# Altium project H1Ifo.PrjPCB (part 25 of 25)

## Sheet IfoSqz5.SchDoc: D1800185
size C; Engineer: Daniel Sigg; DocumentNumber: 10; Revision: 4; SheetNumber: 10; SheetTotal: 10
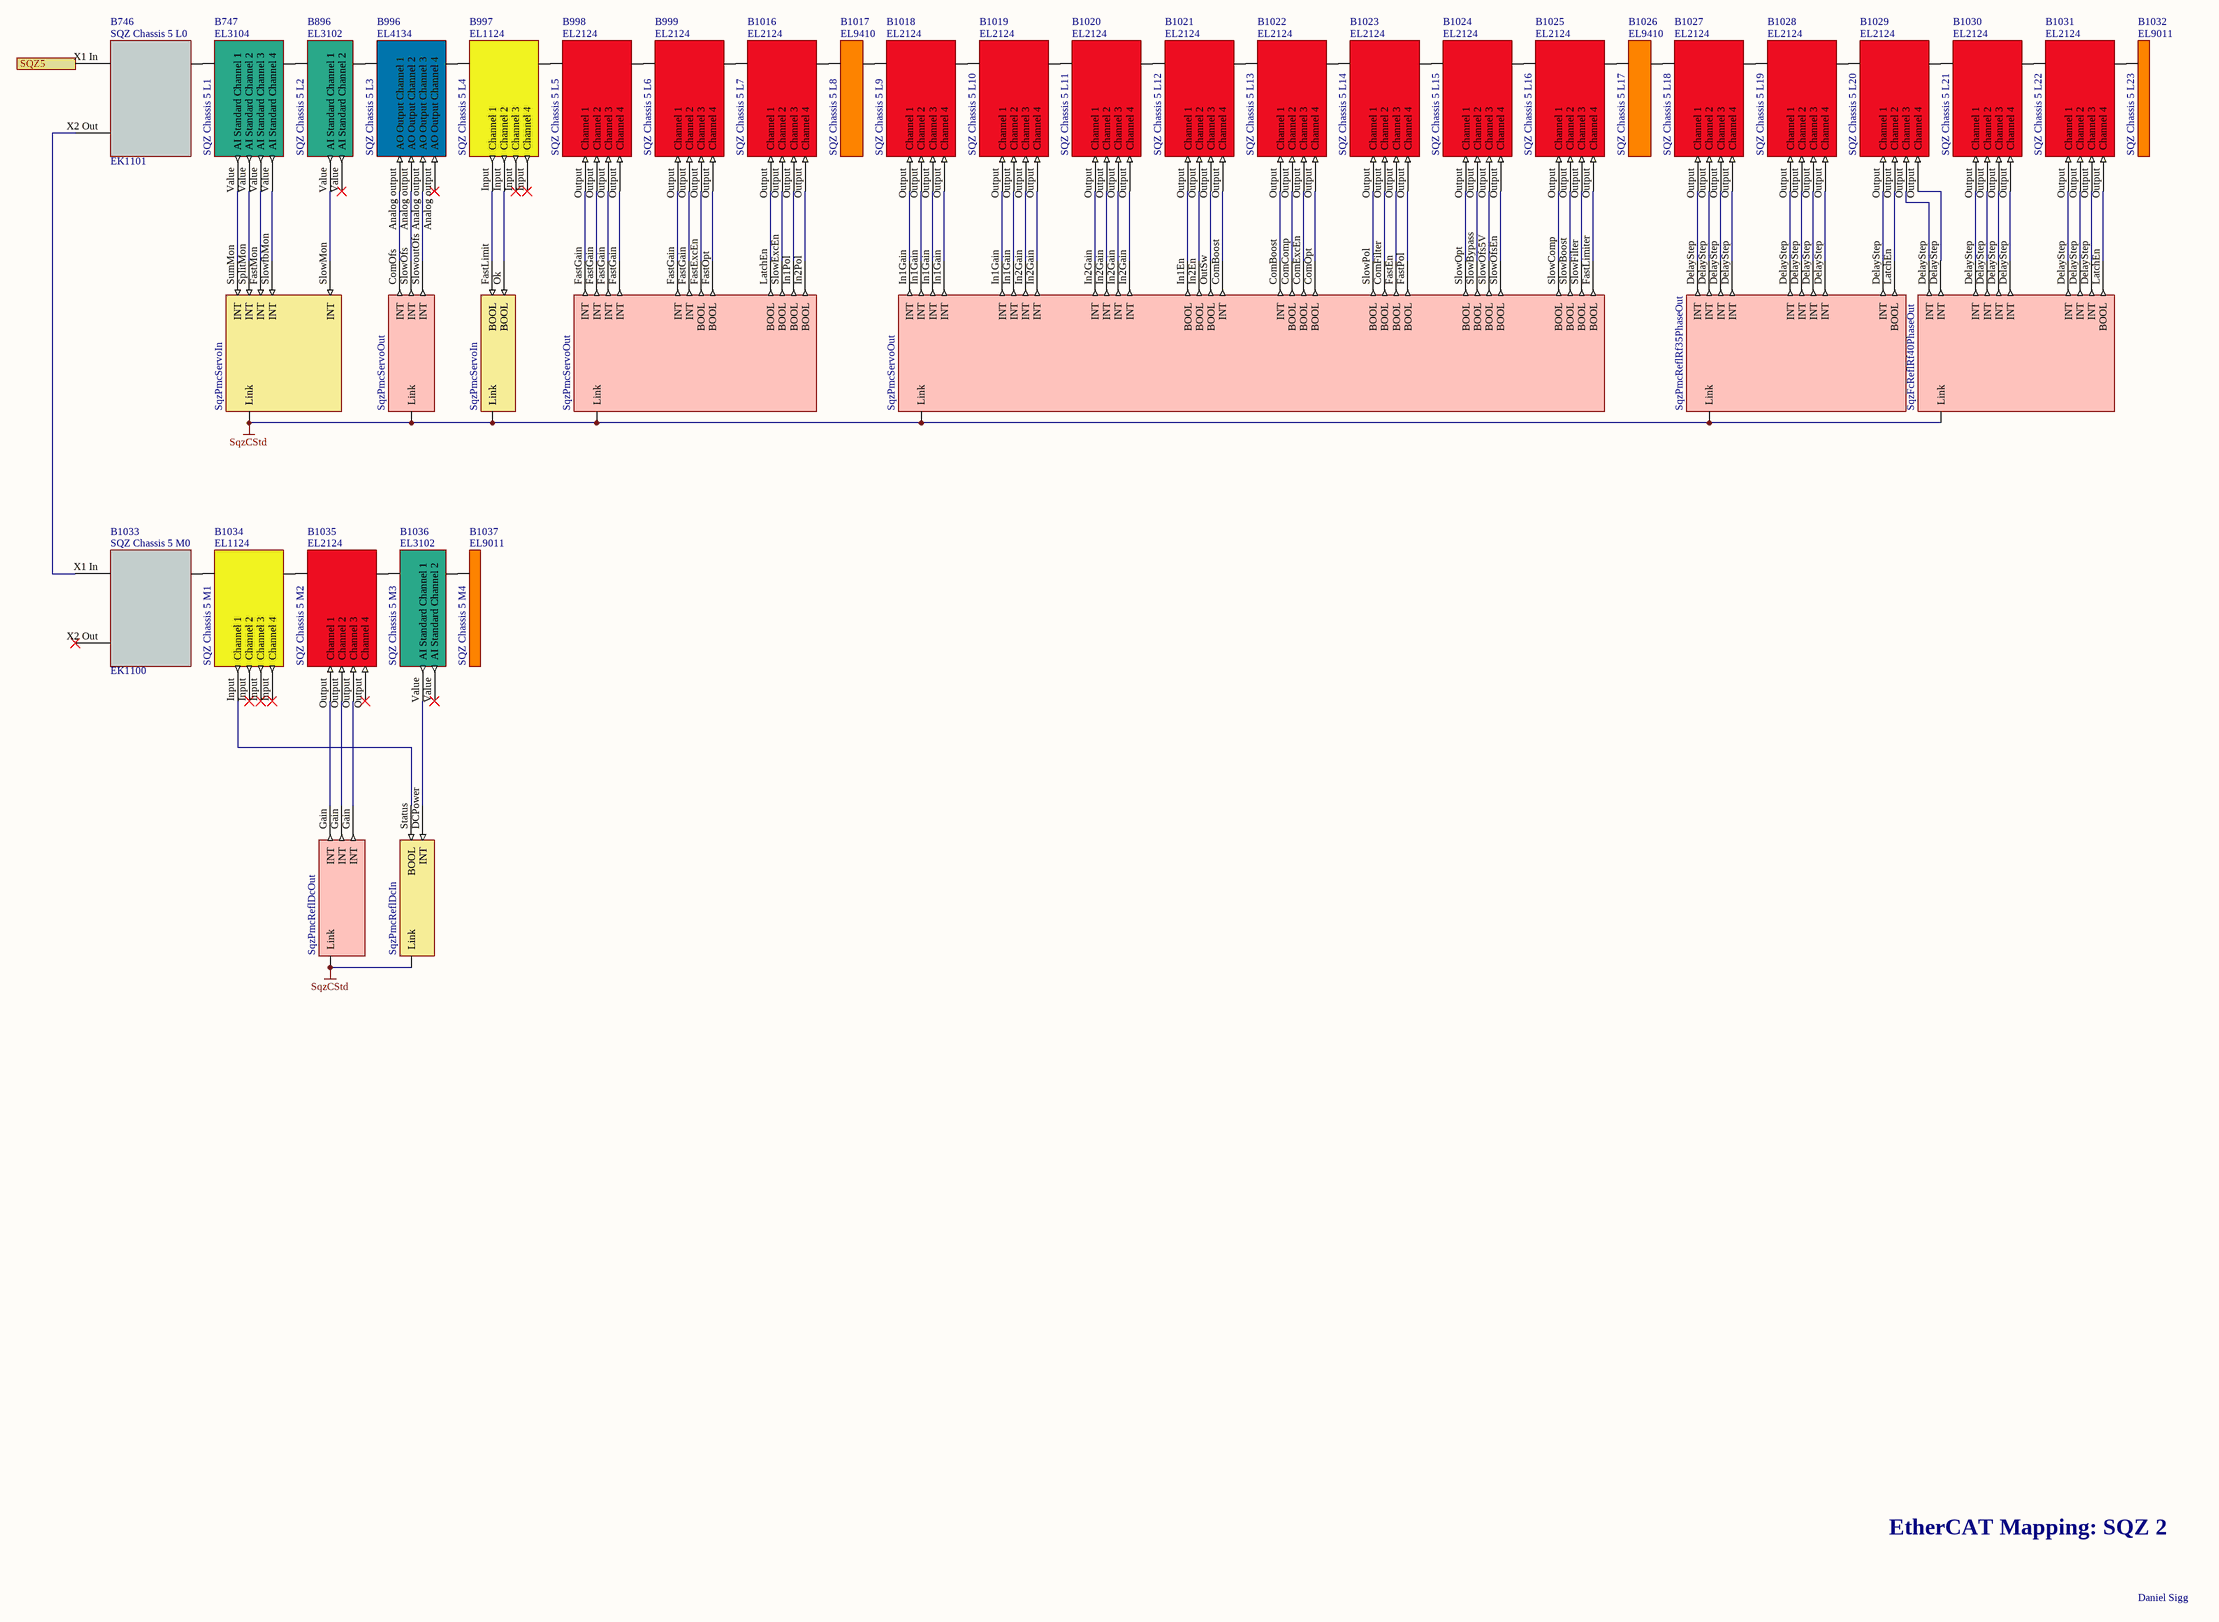
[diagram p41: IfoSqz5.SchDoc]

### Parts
(Parts that share a designator on the sheet are numbered #1, #2 ... from top to bottom, then left to right.)
B746#2  SQZ Chassis 5 L0  Part Number: EK1101
B747#2  SQZ Chassis 5 L1  Part Number: EL3104  (mechanical)
B896#3  SQZ Chassis 5 L2  Part Number: EL3102  (mechanical)
B996#2  SQZ Chassis 5 L3  Part Number: EL4134  (mechanical)
B997#2  SQZ Chassis 5 L4  Part Number: EL1124  (mechanical)
B998#2  SQZ Chassis 5 L5  Part Number: EL2124  (mechanical)
B999#2  SQZ Chassis 5 L6  Part Number: EL2124  (mechanical)
B1016#2  SQZ Chassis 5 L7  Part Number: EL2124  (mechanical)
B1017#2  SQZ Chassis 5 L8  Part Number: EL9410  (mechanical)
B1018#2  SQZ Chassis 5 L9  Part Number: EL2124  (mechanical)
B1019#2  SQZ Chassis 5 L10  Part Number: EL2124  (mechanical)
B1020#3  SQZ Chassis 5 L11  Part Number: EL2124  (mechanical)
B1021#2  SQZ Chassis 5 L12  Part Number: EL2124  (mechanical)
B1022#2  SQZ Chassis 5 L13  Part Number: EL2124  (mechanical)
B1023#2  SQZ Chassis 5 L14  Part Number: EL2124  (mechanical)
B1024#2  SQZ Chassis 5 L15  Part Number: EL2124  (mechanical)
B1025  SQZ Chassis 5 L16  Part Number: EL2124  (mechanical)
B1026  SQZ Chassis 5 L17  Part Number: EL9410  (mechanical)
B1027  SQZ Chassis 5 L18  Part Number: EL2124  (mechanical)
B1028  SQZ Chassis 5 L19  Part Number: EL2124  (mechanical)
B1029  SQZ Chassis 5 L20  Part Number: EL2124  (mechanical)
B1030  SQZ Chassis 5 L21  Part Number: EL2124  (mechanical)
B1031  SQZ Chassis 5 L22  Part Number: EL2124  (mechanical)
B1032  SQZ Chassis 5 L23  Part Number: EL9011  (mechanical)
B1033  SQZ Chassis 5 M0  Part Number: EK1100
B1034  SQZ Chassis 5 M1  Part Number: EL1124  (mechanical)
B1035  SQZ Chassis 5 M2  Part Number: EL2124  (mechanical)
B1036  SQZ Chassis 5 M3  Part Number: EL3102  (mechanical)
B1037  SQZ Chassis 5 M4  Part Number: EL9011  (mechanical)
V868  SqzPmcServoIn  (parts A,B of 2)  (no BOM)
V869  SqzPmcReflRf35PhaseOut  (no BOM)
V870  SqzFcReflRf40PhaseOut  (no BOM)
V871  SqzPmcReflDcOut  (no BOM)
V872  SqzPmcReflDcIn  (no BOM)
V873  SqzPmcServoOut  (parts A,B,C of 3)  (no BOM)

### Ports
SQZ5

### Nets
SqzCStd: V868.0(Link) V868.1(Link) V869.?1(Link) V870.?1(Link) V871.0(Link) V872.1(Link) V873.0(Link) V873.1(Link) V873.2(Link)
NetB746#2_Ebus: B746#2.Ebus(B) B747#2.Ebus(A)
NetB746#2_X1 In: B746#2.X1_In(A) ; port SQZ5
NetB746#2_X2 Out: B746#2.X2_Out(C) B1033.X1_In(A)
NetB747#2_Ebus: B747#2.Ebus(B) B896#3.Ebus(A)
NetB747#2_Value: B747#2.Value(AI_Standard_Channel_1) V868.SumMon(INT)
NetB747#2_Value: B747#2.Value(AI_Standard_Channel_2) V868.SplitMon(INT)  [a separate net that carries the same name]
NetB747#2_Value: B747#2.Value(AI_Standard_Channel_3) V868.FastMon(INT)  [a separate net that carries the same name]
NetB747#2_Value: B747#2.Value(AI_Standard_Channel_4) V868.SlowfbMon(INT)  [a separate net that carries the same name]
NetB896#3_Ebus: B896#3.Ebus(B) B996#2.Ebus(A)
NetB896#3_Value: B896#3.Value(AI_Standard_Channel_1) V868.SlowMon(INT)
NetB996#2_Analog output: B996#2.Analog_output(AO_Output_Channel_1) V873.ComOfs(INT)
NetB996#2_Analog output: B996#2.Analog_output(AO_Output_Channel_2) V873.SlowOfs(INT)  [a separate net that carries the same name]
NetB996#2_Analog output: B996#2.Analog_output(AO_Output_Channel_3) V873.SlowoutOfs(INT)  [a separate net that carries the same name]
NetB996#2_Ebus: B996#2.Ebus(B) B997#2.Ebus(A)
NetB997#2_Ebus: B997#2.Ebus(B) B998#2.Ebus(A)
NetB997#2_Input: B997#2.Input(Channel_1) V868.FastLimit(BOOL)
NetB997#2_Input: B997#2.Input(Channel_2) V868.Ok(BOOL)  [a separate net that carries the same name]
NetB998#2_Ebus: B998#2.Ebus(B) B999#2.Ebus(A)
NetB998#2_Output: B998#2.Output(Channel_1) V873.FastGain(INT)
NetB998#2_Output: B998#2.Output(Channel_2) V873.FastGain(INT)  [a separate net that carries the same name]
NetB998#2_Output: B998#2.Output(Channel_3) V873.FastGain(INT)  [a separate net that carries the same name]
NetB998#2_Output: B998#2.Output(Channel_4) V873.FastGain(INT)  [a separate net that carries the same name]
NetB999#2_Ebus: B999#2.Ebus(B) B1016#2.Ebus(A)
NetB999#2_Output: B999#2.Output(Channel_1) V873.FastGain(INT)
NetB999#2_Output: B999#2.Output(Channel_2) V873.FastGain(INT)  [a separate net that carries the same name]
NetB999#2_Output: B999#2.Output(Channel_3) V873.FastExcEn(BOOL)  [a separate net that carries the same name]
NetB999#2_Output: B999#2.Output(Channel_4) V873.FastOpt(BOOL)  [a separate net that carries the same name]
NetB1016#2_Ebus: B1016#2.Ebus(B) B1017#2.Ebus(A)
NetB1016#2_Output: B1016#2.Output(Channel_1) V873.LatchEn(BOOL)
NetB1016#2_Output: B1016#2.Output(Channel_2) V873.SlowExcEn(BOOL)  [a separate net that carries the same name]
NetB1016#2_Output: B1016#2.Output(Channel_3) V873.In1Pol(BOOL)  [a separate net that carries the same name]
NetB1016#2_Output: B1016#2.Output(Channel_4) V873.In2Pol(BOOL)  [a separate net that carries the same name]
NetB1017#2_Ebus: B1017#2.Ebus(B) B1018#2.Ebus(A)
NetB1018#2_Ebus: B1018#2.Ebus(B) B1019#2.Ebus(A)
NetB1018#2_Output: B1018#2.Output(Channel_1) V873.In1Gain(INT)
NetB1018#2_Output: B1018#2.Output(Channel_2) V873.In1Gain(INT)  [a separate net that carries the same name]
NetB1018#2_Output: B1018#2.Output(Channel_3) V873.In1Gain(INT)  [a separate net that carries the same name]
NetB1018#2_Output: B1018#2.Output(Channel_4) V873.In1Gain(INT)  [a separate net that carries the same name]
NetB1019#2_Ebus: B1019#2.Ebus(B) B1020#3.Ebus(A)
NetB1019#2_Output: B1019#2.Output(Channel_1) V873.In1Gain(INT)
NetB1019#2_Output: B1019#2.Output(Channel_2) V873.In1Gain(INT)  [a separate net that carries the same name]
NetB1019#2_Output: B1019#2.Output(Channel_3) V873.In2Gain(INT)  [a separate net that carries the same name]
NetB1019#2_Output: B1019#2.Output(Channel_4) V873.In2Gain(INT)  [a separate net that carries the same name]
NetB1020#3_Ebus: B1020#3.Ebus(B) B1021#2.Ebus(A)
NetB1020#3_Output: B1020#3.Output(Channel_1) V873.In2Gain(INT)
NetB1020#3_Output: B1020#3.Output(Channel_2) V873.In2Gain(INT)  [a separate net that carries the same name]
NetB1020#3_Output: B1020#3.Output(Channel_3) V873.In2Gain(INT)  [a separate net that carries the same name]
NetB1020#3_Output: B1020#3.Output(Channel_4) V873.In2Gain(INT)  [a separate net that carries the same name]
NetB1021#2_Ebus: B1021#2.Ebus(B) B1022#2.Ebus(A)
NetB1021#2_Output: B1021#2.Output(Channel_1) V873.In1En(BOOL)
NetB1021#2_Output: B1021#2.Output(Channel_2) V873.In2En(BOOL)  [a separate net that carries the same name]
NetB1021#2_Output: B1021#2.Output(Channel_3) V873.OutSw(BOOL)  [a separate net that carries the same name]
NetB1021#2_Output: B1021#2.Output(Channel_4) V873.ComBoost(INT)  [a separate net that carries the same name]
NetB1022#2_Ebus: B1022#2.Ebus(B) B1023#2.Ebus(A)
NetB1022#2_Output: B1022#2.Output(Channel_1) V873.ComBoost(INT)
NetB1022#2_Output: B1022#2.Output(Channel_2) V873.ComComp(BOOL)  [a separate net that carries the same name]
NetB1022#2_Output: B1022#2.Output(Channel_3) V873.ComExcEn(BOOL)  [a separate net that carries the same name]
NetB1022#2_Output: B1022#2.Output(Channel_4) V873.ComOpt(BOOL)  [a separate net that carries the same name]
NetB1023#2_Ebus: B1023#2.Ebus(B) B1024#2.Ebus(A)
NetB1023#2_Output: B1023#2.Output(Channel_1) V873.SlowPol(BOOL)
NetB1023#2_Output: B1023#2.Output(Channel_2) V873.ComFilter(BOOL)  [a separate net that carries the same name]
NetB1023#2_Output: B1023#2.Output(Channel_3) V873.FastEn(BOOL)  [a separate net that carries the same name]
NetB1023#2_Output: B1023#2.Output(Channel_4) V873.FastPol(BOOL)  [a separate net that carries the same name]
NetB1024#2_Ebus: B1024#2.Ebus(B) B1025.Ebus(A)
NetB1024#2_Output: B1024#2.Output(Channel_1) V873.SlowOpt(BOOL)
NetB1024#2_Output: B1024#2.Output(Channel_2) V873.SlowBypass(BOOL)  [a separate net that carries the same name]
NetB1024#2_Output: B1024#2.Output(Channel_3) V873.SlowOfs5V(BOOL)  [a separate net that carries the same name]
NetB1024#2_Output: B1024#2.Output(Channel_4) V873.SlowOfsEn(BOOL)  [a separate net that carries the same name]
NetB1025_Ebus: B1025.Ebus(B) B1026.Ebus(A)
NetB1025_Output: B1025.Output(Channel_1) V873.SlowComp(BOOL)
NetB1025_Output: B1025.Output(Channel_2) V873.SlowBoost(BOOL)  [a separate net that carries the same name]
NetB1025_Output: B1025.Output(Channel_3) V873.SlowFilter(BOOL)  [a separate net that carries the same name]
NetB1025_Output: B1025.Output(Channel_4) V873.FastLimiter(BOOL)  [a separate net that carries the same name]
NetB1026_Ebus: B1026.Ebus(B) B1027.Ebus(A)
NetB1027_Ebus: B1027.Ebus(B) B1028.Ebus(A)
NetB1027_Output: B1027.Output(Channel_1) V869.DelayStep(INT)
NetB1027_Output: B1027.Output(Channel_2) V869.DelayStep(INT)  [a separate net that carries the same name]
NetB1027_Output: B1027.Output(Channel_3) V869.DelayStep(INT)  [a separate net that carries the same name]
NetB1027_Output: B1027.Output(Channel_4) V869.DelayStep(INT)  [a separate net that carries the same name]
NetB1028_Ebus: B1028.Ebus(B) B1029.Ebus(A)
NetB1028_Output: B1028.Output(Channel_1) V869.DelayStep(INT)
NetB1028_Output: B1028.Output(Channel_2) V869.DelayStep(INT)  [a separate net that carries the same name]
NetB1028_Output: B1028.Output(Channel_3) V869.DelayStep(INT)  [a separate net that carries the same name]
NetB1028_Output: B1028.Output(Channel_4) V869.DelayStep(INT)  [a separate net that carries the same name]
NetB1029_Ebus: B1029.Ebus(B) B1030.Ebus(A)
NetB1029_Output: B1029.Output(Channel_1) V869.DelayStep(INT)
NetB1029_Output: B1029.Output(Channel_2) V869.LatchEn(BOOL)  [a separate net that carries the same name]
NetB1029_Output: B1029.Output(Channel_3) V870.DelayStep(INT)  [a separate net that carries the same name]
NetB1029_Output: B1029.Output(Channel_4) V870.DelayStep(INT)  [a separate net that carries the same name]
NetB1030_Ebus: B1030.Ebus(B) B1031.Ebus(A)
NetB1030_Output: B1030.Output(Channel_1) V870.DelayStep(INT)
NetB1030_Output: B1030.Output(Channel_2) V870.DelayStep(INT)  [a separate net that carries the same name]
NetB1030_Output: B1030.Output(Channel_3) V870.DelayStep(INT)  [a separate net that carries the same name]
NetB1030_Output: B1030.Output(Channel_4) V870.DelayStep(INT)  [a separate net that carries the same name]
NetB1031_Ebus: B1031.Ebus(B) B1032.Ebus(A)
NetB1031_Output: B1031.Output(Channel_1) V870.DelayStep(INT)
NetB1031_Output: B1031.Output(Channel_2) V870.DelayStep(INT)  [a separate net that carries the same name]
NetB1031_Output: B1031.Output(Channel_3) V870.DelayStep(INT)  [a separate net that carries the same name]
NetB1031_Output: B1031.Output(Channel_4) V870.LatchEn(BOOL)  [a separate net that carries the same name]
NetB1033_Ebus: B1033.Ebus(B) B1034.Ebus(A)
NetB1034_Ebus: B1034.Ebus(B) B1035.Ebus(A)
NetB1034_Input: B1034.Input(Channel_1) V872.Status(BOOL)
NetB1035_Ebus: B1035.Ebus(B) B1036.Ebus(A)
NetB1035_Output: B1035.Output(Channel_1) V871.Gain(INT)
NetB1035_Output: B1035.Output(Channel_2) V871.Gain(INT)  [a separate net that carries the same name]
NetB1035_Output: B1035.Output(Channel_3) V871.Gain(INT)  [a separate net that carries the same name]
NetB1036_Ebus: B1036.Ebus(B) B1037.Ebus(A)
NetB1036_Value: B1036.Value(AI_Standard_Channel_1) V872.DCPower(INT)

Not connected (* = marked no-connect by the designer): B1033 X2 Out(C)*

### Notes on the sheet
- EtherCAT Mapping: SQZ 2
- Daniel Sigg

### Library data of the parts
B746#2 = CouplerEK1101: EtherCAT Coupler; Rail: Left; BoxNextB: LKYXOSUU; BoxNextC: LKDMUIJW; BoxPrev: CWDKXLUE; PortPrevFull: 1240/C; PortPrevShort: C 'X2 Out'; Fullname: TIID^Vertex Squeezer (EtherCAT)^SQZ Chassis 5 L0 (EK1101); BoxPorts: Junction; BoxAddr: 1253; Disabled: False
B747#2 = TerminalEL3104: EtherCAT Terminal EL3104 4-chn Analog Input; Rail: Left; BoxNextB: JVLGVOLS; BoxPrev: JQVLJOFM; PortPrevFull: 1253/B; PortPrevShort: B; Fullname: TIID^Vertex Squeezer (EtherCAT)^SQZ Chassis 5 L0 (EK1101)^SQZ Chassis 5 L1 (EL3104); BoxAddr: 1254; Disabled: False
B896#3 = TerminalEL3102: EtherCAT Terminal EL3102 2-chn Analog Input; Rail: Left; BoxNextB: BEMJPELD; BoxPrev: LKYXOSUU; PortPrevFull: 1254/B; PortPrevShort: B; Fullname: TIID^Vertex Squeezer (EtherCAT)^SQZ Chassis 5 L0 (EK1101)^SQZ Chassis 5 L2 (EL3102); BoxAddr: 1255; Disabled: False
B996#2 = TerminalEL4134: EtherCAT Terminal EL4134 4-chn Analog Ouput; Rail: Left; BoxNextB: KFGECLUF; BoxPrev: JVLGVOLS; PortPrevFull: 1255/B; PortPrevShort: B; Fullname: TIID^Vertex Squeezer (EtherCAT)^SQZ Chassis 5 L0 (EK1101)^SQZ Chassis 5 L3 (EL4134); BoxAddr: 1256; Disabled: False
B997#2 = TerminalEL1124: EtherCAT Terminal EL1124 4-chn Digital Input; Rail: Left; BoxNextB: XXYSQFDN; BoxPrev: BEMJPELD; PortPrevFull: 1256/B; PortPrevShort: B; Fullname: TIID^Vertex Squeezer (EtherCAT)^SQZ Chassis 5 L0 (EK1101)^SQZ Chassis 5 L4 (EL1124); BoxAddr: 1257; Disabled: False
B998#2 = TerminalEL2124: EtherCAT Terminal EL2124 4-chn Digital Ouput; Rail: Left; BoxNextB: NKADTWFC; BoxPrev: KFGECLUF; PortPrevFull: 1257/B; PortPrevShort: B; Fullname: TIID^Vertex Squeezer (EtherCAT)^SQZ Chassis 5 L0 (EK1101)^SQZ Chassis 5 L5 (EL2124); BoxAddr: 1258; Disabled: False
B999#2 = TerminalEL2124: EtherCAT Terminal EL2124 4-chn Digital Ouput; Rail: Left; BoxNextB: BBCHXAVO; BoxPrev: XXYSQFDN; PortPrevFull: 1258/B; PortPrevShort: B; Fullname: TIID^Vertex Squeezer (EtherCAT)^SQZ Chassis 5 L0 (EK1101)^SQZ Chassis 5 L6 (EL2124); BoxAddr: 1259; Disabled: False
B1016#2 = TerminalEL2124: EtherCAT Terminal EL2124 4-chn Digital Ouput; Rail: Left; BoxNextB: KRYXCAPR; BoxPrev: NKADTWFC; PortPrevFull: 1259/B; PortPrevShort: B; Fullname: TIID^Vertex Squeezer (EtherCAT)^SQZ Chassis 5 L0 (EK1101)^SQZ Chassis 5 L7 (EL2124); BoxAddr: 1260; Disabled: False
B1017#2 = TerminalEL9410: EtherCAT Terminal EL9410 Power; Rail: Left; BoxNextB: IYADOACW; BoxPrev: BBCHXAVO; PortPrevFull: 1260/B; PortPrevShort: B; Fullname: TIID^Vertex Squeezer (EtherCAT)^SQZ Chassis 5 L0 (EK1101)^SQZ Chassis 5 L8 (EL9410); BoxAddr: 1261; Disabled: False
B1018#2 = TerminalEL2124: EtherCAT Terminal EL2124 4-chn Digital Ouput; Rail: Left; BoxNextB: FWAQFTHP; BoxPrev: KRYXCAPR; PortPrevFull: 1261/B; PortPrevShort: B; Fullname: TIID^Vertex Squeezer (EtherCAT)^SQZ Chassis 5 L0 (EK1101)^SQZ Chassis 5 L9 (EL2124); BoxAddr: 1262; Disabled: False
B1019#2 = TerminalEL2124: EtherCAT Terminal EL2124 4-chn Digital Ouput; Rail: Left; BoxNextB: YNBMSKFQ; BoxPrev: IYADOACW; PortPrevFull: 1262/B; PortPrevShort: B; Fullname: TIID^Vertex Squeezer (EtherCAT)^SQZ Chassis 5 L0 (EK1101)^SQZ Chassis 5 L10 (EL2124); BoxAddr: 1263; Disabled: False
B1020#3 = TerminalEL2124: EtherCAT Terminal EL2124 4-chn Digital Ouput; Rail: Left; BoxNextB: RSFOLQSB; BoxPrev: FWAQFTHP; PortPrevFull: 1263/B; PortPrevShort: B; Fullname: TIID^Vertex Squeezer (EtherCAT)^SQZ Chassis 5 L0 (EK1101)^SQZ Chassis 5 L11 (EL2124); BoxAddr: 1264; Disabled: False
B1021#2 = TerminalEL2124: EtherCAT Terminal EL2124 4-chn Digital Ouput; Rail: Left; BoxNextB: WUOQKASJ; BoxPrev: YNBMSKFQ; PortPrevFull: 1264/B; PortPrevShort: B; Fullname: TIID^Vertex Squeezer (EtherCAT)^SQZ Chassis 5 L0 (EK1101)^SQZ Chassis 5 L12 (EL2124); BoxAddr: 1265; Disabled: False
B1022#2 = TerminalEL2124: EtherCAT Terminal EL2124 4-chn Digital Ouput; Rail: Left; BoxNextB: RPVQQTWJ; BoxPrev: RSFOLQSB; PortPrevFull: 1265/B; PortPrevShort: B; Fullname: TIID^Vertex Squeezer (EtherCAT)^SQZ Chassis 5 L0 (EK1101)^SQZ Chassis 5 L13 (EL2124); BoxAddr: 1266; Disabled: False
B1023#2 = TerminalEL2124: EtherCAT Terminal EL2124 4-chn Digital Ouput; Rail: Left; BoxNextB: MLVVBFMT; BoxPrev: WUOQKASJ; PortPrevFull: 1266/B; PortPrevShort: B; Fullname: TIID^Vertex Squeezer (EtherCAT)^SQZ Chassis 5 L0 (EK1101)^SQZ Chassis 5 L14 (EL2124); BoxAddr: 1267; Disabled: False
B1024#2 = TerminalEL2124: EtherCAT Terminal EL2124 4-chn Digital Ouput; Rail: Left; BoxNextB: SGWXRRPH; BoxPrev: RPVQQTWJ; PortPrevFull: 1267/B; PortPrevShort: B; Fullname: TIID^Vertex Squeezer (EtherCAT)^SQZ Chassis 5 L0 (EK1101)^SQZ Chassis 5 L15 (EL2124); BoxAddr: 1268; Disabled: False
B1025 = TerminalEL2124: EtherCAT Terminal EL2124 4-chn Digital Ouput; Rail: Left; BoxNextB: CTCISQMT; BoxPrev: MLVVBFMT; PortPrevFull: 1268/B; PortPrevShort: B; Fullname: TIID^Vertex Squeezer (EtherCAT)^SQZ Chassis 5 L0 (EK1101)^SQZ Chassis 5 L16 (EL2124); BoxAddr: 1269; Disabled: False
B1026 = TerminalEL9410: EtherCAT Terminal EL9410 Power; Rail: Left; BoxNextB: AVCHSOEV; BoxPrev: SGWXRRPH; PortPrevFull: 1269/B; PortPrevShort: B; Fullname: TIID^Vertex Squeezer (EtherCAT)^SQZ Chassis 5 L0 (EK1101)^SQZ Chassis 5 L17 (EL9410); BoxAddr: 1270; Disabled: False
B1027 = TerminalEL2124: EtherCAT Terminal EL2124 4-chn Digital Ouput; Rail: Left; BoxNextB: RNOAQAFY; BoxPrev: CTCISQMT; PortPrevFull: 1270/B; PortPrevShort: B; Fullname: TIID^Vertex Squeezer (EtherCAT)^SQZ Chassis 5 L0 (EK1101)^SQZ Chassis 5 L18 (EL2124); BoxAddr: 1271; Disabled: False
B1028 = TerminalEL2124: EtherCAT Terminal EL2124 4-chn Digital Ouput; Rail: Left; BoxNextB: MVUKHKFD; BoxPrev: AVCHSOEV; PortPrevFull: 1271/B; PortPrevShort: B; Fullname: TIID^Vertex Squeezer (EtherCAT)^SQZ Chassis 5 L0 (EK1101)^SQZ Chassis 5 L19 (EL2124); BoxAddr: 1272; Disabled: False
B1029 = TerminalEL2124: EtherCAT Terminal EL2124 4-chn Digital Ouput; Rail: Left; BoxNextB: BATIWAGG; BoxPrev: RNOAQAFY; PortPrevFull: 1272/B; PortPrevShort: B; Fullname: TIID^Vertex Squeezer (EtherCAT)^SQZ Chassis 5 L0 (EK1101)^SQZ Chassis 5 L20 (EL2124); BoxAddr: 1273; Disabled: False
B1030 = TerminalEL2124: EtherCAT Terminal EL2124 4-chn Digital Ouput; Rail: Left; BoxNextB: OYHVUHQP; BoxPrev: MVUKHKFD; PortPrevFull: 1273/B; PortPrevShort: B; Fullname: TIID^Vertex Squeezer (EtherCAT)^SQZ Chassis 5 L0 (EK1101)^SQZ Chassis 5 L21 (EL2124); BoxAddr: 1274; Disabled: False
B1031 = TerminalEL2124: EtherCAT Terminal EL2124 4-chn Digital Ouput; Rail: Left; BoxNextB: ODKNBTAG; BoxPrev: BATIWAGG; PortPrevFull: 1274/B; PortPrevShort: B; Fullname: TIID^Vertex Squeezer (EtherCAT)^SQZ Chassis 5 L0 (EK1101)^SQZ Chassis 5 L22 (EL2124); BoxAddr: 1275; Disabled: False
B1032 = TerminalEL9011: EtherCAT Terminal EL9011 End; BoxType: TerminalPassive; Rail: Left; BoxPrev: OYHVUHQP; PortPrevShort: B; Fullname: TIID^Vertex Squeezer (EtherCAT)^SQZ Chassis 5 L0 (EK1101)^SQZ Chassis 5 L23 (EL9011); Disabled: False
B1033 = CouplerEK1100: EtherCAT Coupler; Rail: Middle; BoxNextB: FLDENWVA; BoxPrev: JQVLJOFM; PortPrevFull: 1253/C; PortPrevShort: C 'X2 Out'; Fullname: TIID^Vertex Squeezer (EtherCAT)^SQZ Chassis 5 M0 (EK1100); BoxPorts: Junction; BoxAddr: 1276; Disabled: False
B1034 = TerminalEL1124: EtherCAT Terminal EL1124 4-chn Digital Input; Rail: Middle; BoxNextB: PTDDMXXB; BoxPrev: LKDMUIJW; PortPrevFull: 1276/B; PortPrevShort: B; Fullname: TIID^Vertex Squeezer (EtherCAT)^SQZ Chassis 5 M0 (EK1100)^SQZ Chassis 5 M1 (EL1124); BoxAddr: 1277; Disabled: False
B1035 = TerminalEL2124: EtherCAT Terminal EL2124 4-chn Digital Ouput; Rail: Middle; BoxNextB: PCGSTQTN; BoxPrev: FLDENWVA; PortPrevFull: 1277/B; PortPrevShort: B; Fullname: TIID^Vertex Squeezer (EtherCAT)^SQZ Chassis 5 M0 (EK1100)^SQZ Chassis 5 M2 (EL2124); BoxAddr: 1278; Disabled: False
B1036 = TerminalEL3102: EtherCAT Terminal EL3102 2-chn Analog Input; Rail: Middle; BoxNextB: FMNHAXUQ; BoxPrev: PTDDMXXB; PortPrevFull: 1278/B; PortPrevShort: B; Fullname: TIID^Vertex Squeezer (EtherCAT)^SQZ Chassis 5 M0 (EK1100)^SQZ Chassis 5 M3 (EL3102); BoxAddr: 1279; Disabled: False
B1037 = TerminalEL9011: EtherCAT Terminal EL9011 End; BoxType: TerminalPassive; Rail: Middle; BoxPrev: PCGSTQTN; PortPrevShort: B; Fullname: TIID^Vertex Squeezer (EtherCAT)^SQZ Chassis 5 M0 (EK1100)^SQZ Chassis 5 M4 (EL9011); Disabled: False
V868 = CommonMode_CommonModeInStructB: CommonModeInStruct; BoxType: Variable; Instance: H1SqzCorner Instance; PLC: H1SqzCorner; Task: SqzCStd
V869 = DelayLogic_DelayLogicOutStruct: DelayLogicOutStruct; BoxType: Variable; Instance: H1SqzCorner Instance; PLC: H1SqzCorner; Task: SqzCStd
V870 = DelayLogic_DelayLogicOutStructB: DelayLogicOutStruct; BoxType: Variable; Instance: H1SqzCorner Instance; PLC: H1SqzCorner; Task: SqzCStd
V871 = DCPower_DCPowerOutStructLegacy: DCPowerOutStruct; BoxType: Variable; Instance: H1SqzCorner Instance; PLC: H1SqzCorner; Task: SqzCStd
V872 = DCPower_DCPowerInStructLegacy: DCPowerInStruct; BoxType: Variable; Instance: H1SqzCorner Instance; PLC: H1SqzCorner; Task: SqzCStd
V873 = CommonMode_CommonModeOutStructC: CommonModeOutStruct; BoxType: Variable; Instance: H1SqzCorner Instance; PLC: H1SqzCorner; Task: SqzCStd

## Sheet IfoTop1.SchDoc: D1800185
size C; DocumentNumber: 2; Revision: 4; SheetNumber: 2; SheetTotal: 31; pInstance: Corner
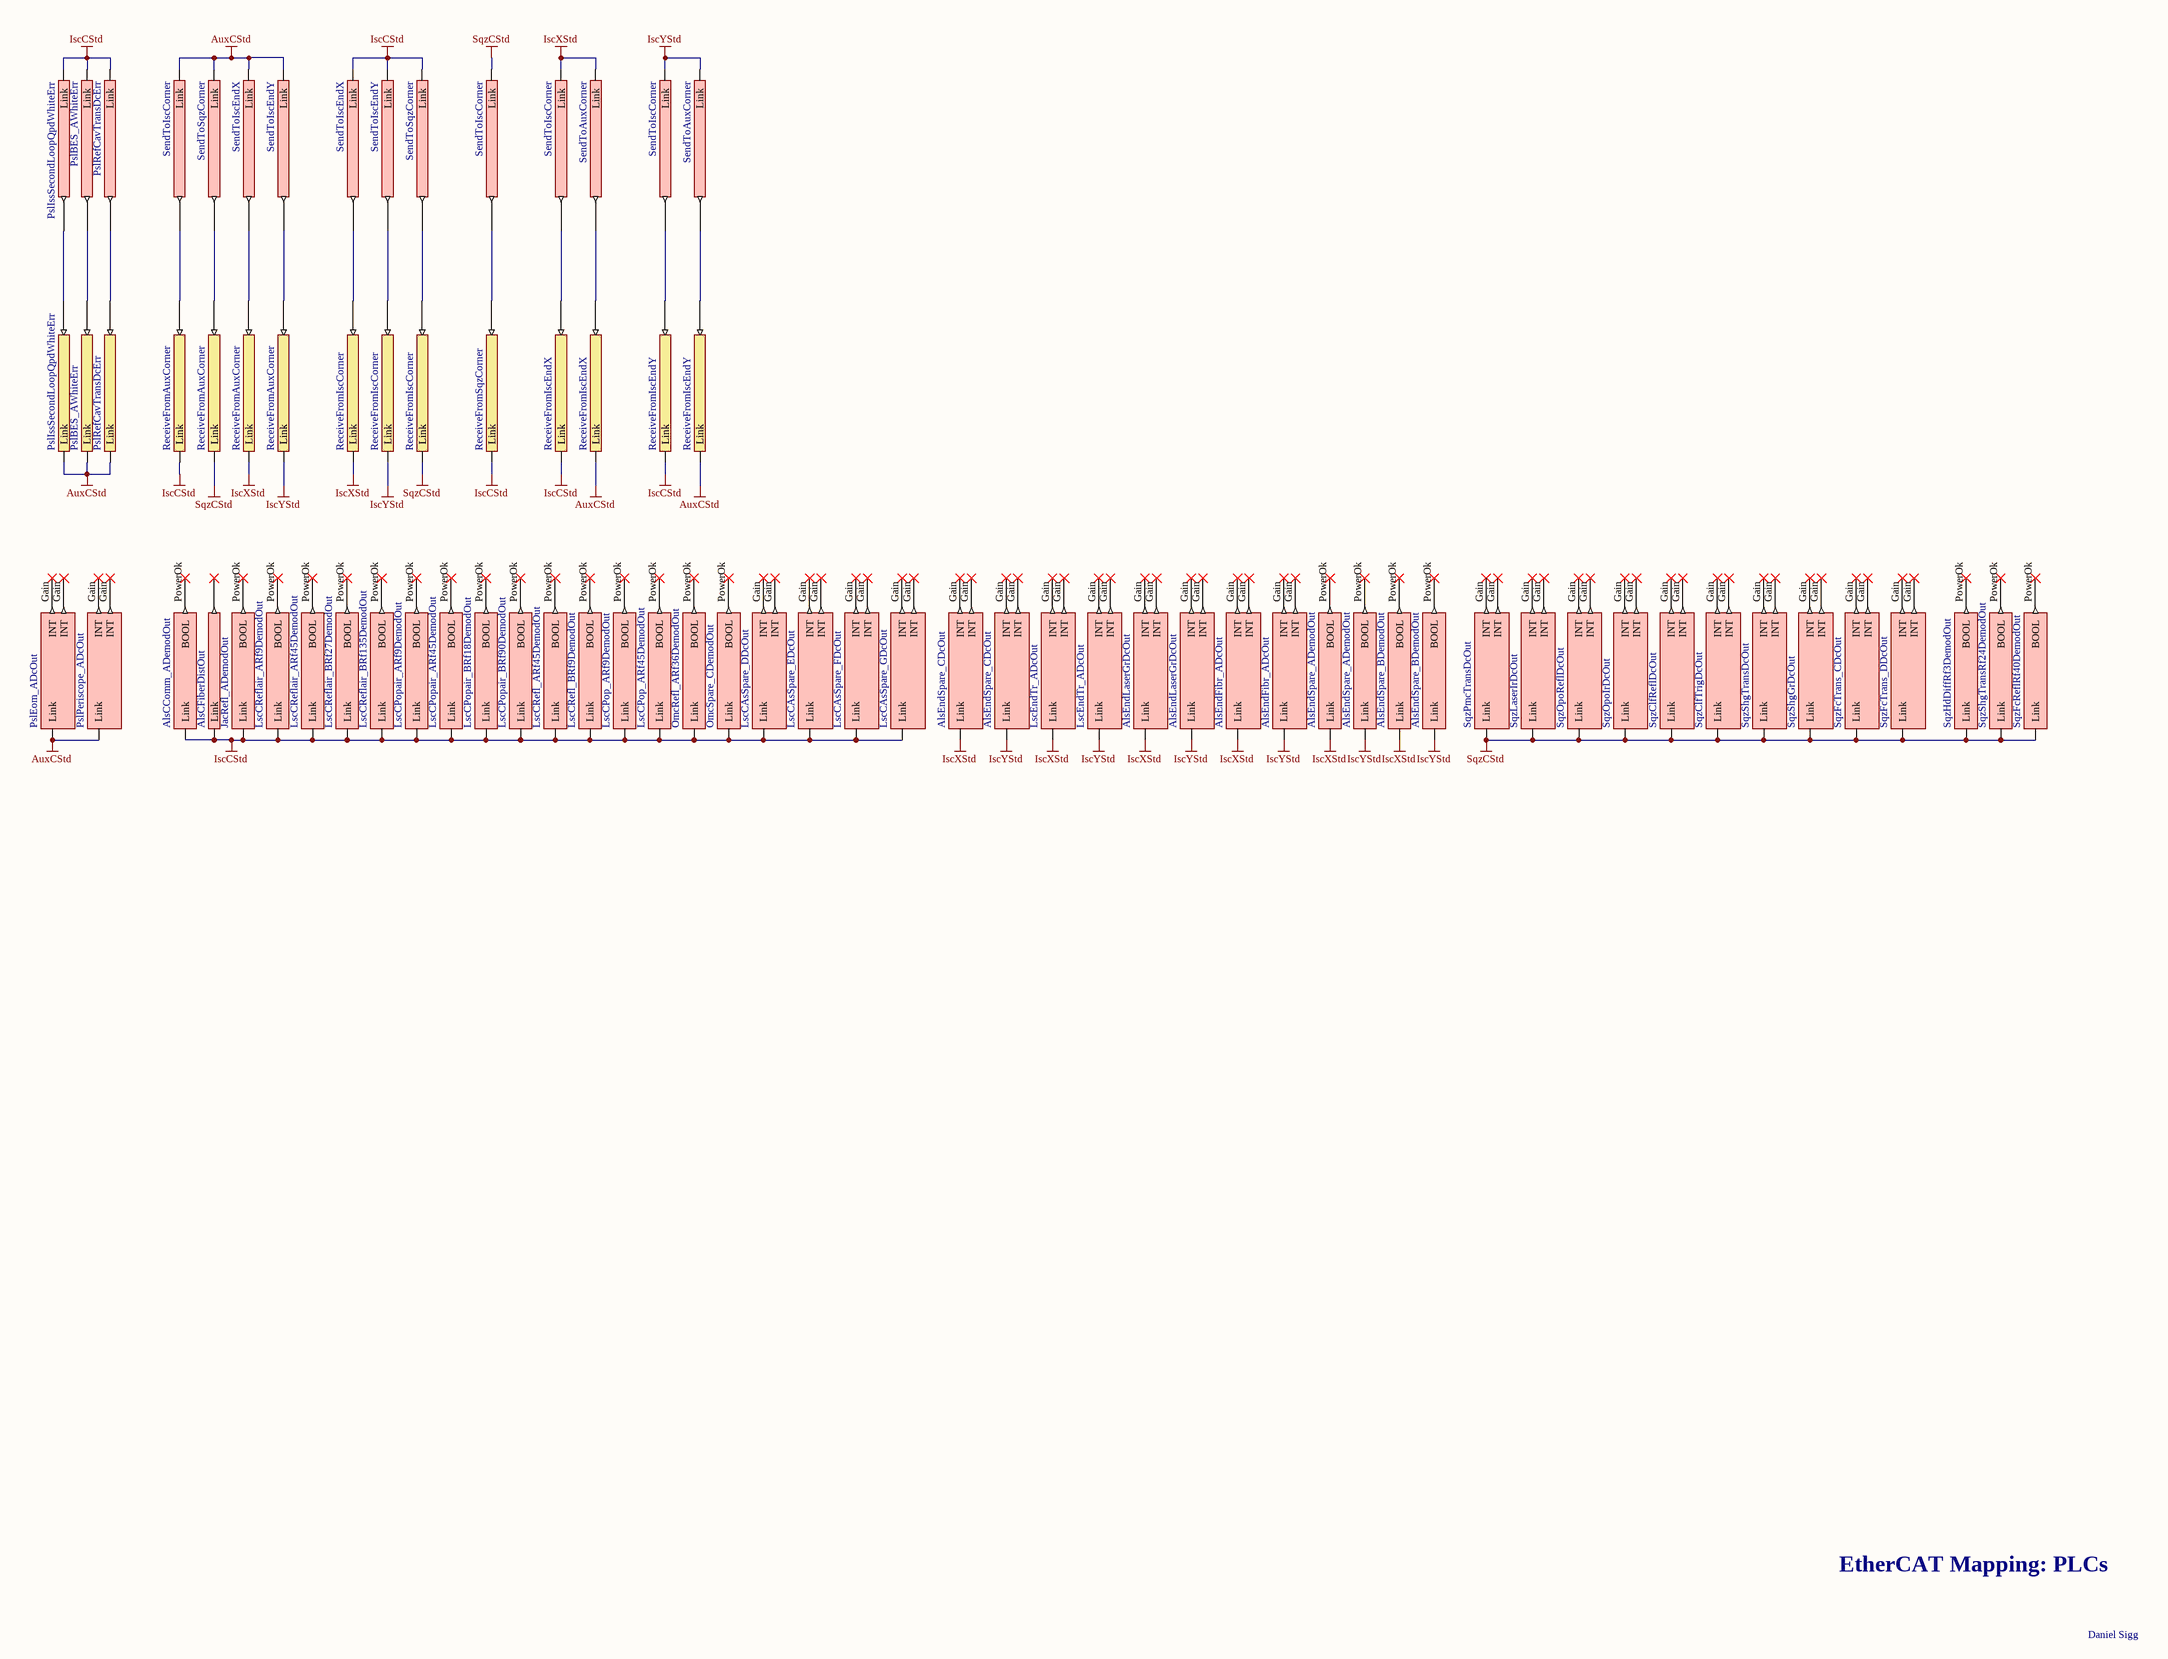
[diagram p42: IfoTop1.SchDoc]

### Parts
V1  PslIssSecondLoopQpdWhiteErr  (no BOM)
V2  PslBES_AWhiteErr  (no BOM)
V3  PslRefCavTransDcErr  (no BOM)
V4  SendToIscCorner  (no BOM)
V5  SendToSqzCorner  (no BOM)
V6  SendToIscEndX  (no BOM)
V7  SendToIscEndY  (no BOM)
V8  SendToIscEndX  (no BOM)
V9  SendToIscEndY  (no BOM)
V10  SendToSqzCorner  (no BOM)
V11  SendToAuxCorner  (no BOM)
V12  SendToAuxCorner  (no BOM)
V13  SendToIscCorner  (no BOM)
V14  SendToIscCorner  (no BOM)
V15  SendToIscCorner  (no BOM)
V16  PslIssSecondLoopQpdWhiteErr  (no BOM)
V17  PslBES_AWhiteErr  (no BOM)
V18  PslRefCavTransDcErr  (no BOM)
V19  ReceiveFromAuxCorner  (no BOM)
V20  ReceiveFromAuxCorner  (no BOM)
V21  ReceiveFromAuxCorner  (no BOM)
V22  ReceiveFromAuxCorner  (no BOM)
V23  ReceiveFromIscCorner  (no BOM)
V24  ReceiveFromIscCorner  (no BOM)
V26  ReceiveFromIscCorner  (no BOM)
V27  ReceiveFromIscEndX  (no BOM)
V28  ReceiveFromIscEndY  (no BOM)
V29  ReceiveFromSqzCorner  (no BOM)
V30  ReceiveFromIscEndX  (no BOM)
V31  ReceiveFromIscEndY  (no BOM)
V32  PslEom_ADcOut  (no BOM)
V33  PslPeriscope_ADcOut  (no BOM)
V34  AlsCComm_ADemodOut  (no BOM)
V35  AlsCFiberDistOut  (no BOM)
V36  JacRefl_ADemodOut  (no BOM)
V37  LscCReflair_ARf9DemodOut  (no BOM)
V38  LscCReflair_ARf45DemodOut  (no BOM)
V39  LscCReflair_BRf27DemodOut  (no BOM)
V40  LscCReflair_BRf135DemodOut  (no BOM)
V41  LscCPopair_ARf9DemodOut  (no BOM)
V42  LscCPopair_ARf45DemodOut  (no BOM)
V43  LscCPopair_BRf18DemodOut  (no BOM)
V44  LscCPopair_BRf90DemodOut  (no BOM)
V45  LscCRefl_ARf45DemodOut  (no BOM)
V46  LscCPop_ARf9DemodOut  (no BOM)
V47  LscCPop_ARf45DemodOut  (no BOM)
V48  AlsEndSpare_CDcOut  (no BOM)
V52  AlsEndSpare_CDcOut  (no BOM)
V53  LscEndTr_ADcOut  (no BOM)
V54  LscEndTr_ADcOut  (no BOM)
V55  AlsEndLaserGrDcOut  (no BOM)
V56  AlsEndLaserGrDcOut  (no BOM)
V57  AlsEndFibr_ADcOut  (no BOM)
V58  AlsEndFibr_ADcOut  (no BOM)
V59  AlsEndSpare_ADemodOut  (no BOM)
V60  AlsEndSpare_ADemodOut  (no BOM)
V61  AlsEndSpare_BDemodOut  (no BOM)
V65  AlsEndSpare_BDemodOut  (no BOM)
V66  SqzLaserIrDcOut  (no BOM)
V67  SqzPmcTransDcOut  (no BOM)
V69  SqzOpoReflDcOut  (no BOM)
V70  SqzOpoIrDcOut  (no BOM)
V71  SqzClfReflDcOut  (no BOM)
V72  SqzClfTrigDcOut  (no BOM)
V73  SqzShgTransDcOut  (no BOM)
V77  SqzShgGrDcOut  (no BOM)
V78  SqzHdDiffRf3DemodOut  (no BOM)
V79  SqzShgTransRf24DemodOut  (no BOM)
V80  SqzFcReflRf40DemodOut  (no BOM)
V740  LscCAsSpare_EDcOut  (no BOM)
V741  LscCAsSpare_FDcOut  (no BOM)
V742  LscCAsSpare_GDcOut  (no BOM)
V743  LscCAsSpare_DDcOut  (no BOM)
V840  SqzFcTrans_DDcOut  (no BOM)
V841  SqzFcTrans_CDcOut  (no BOM)
V877  LscCRefl_BRf9DemodOut  (no BOM)
V894  OmcRefl_ARf36DemodOut  (no BOM)
V895  OmcSpare_CDemodOut  (no BOM)

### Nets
AuxCStd: V4.?2(Link) V5.?2(Link) V6.?2(Link) V7.?2(Link) V16.?2(Link) V17.?2(Link) V18.?2(Link) V27.?2(Link) V28.?2(Link) V32.0(Link) V33.0(Link)
IscCStd: V1.?2(Link) V2.?2(Link) V3.?2(Link) V8.?2(Link) V9.?2(Link) V10.?2(Link) V19.?2(Link) V29.?2(Link) V30.?2(Link) V31.?2(Link) V34.?1(Link) V35.?2(Link) V36.?1(Link) V37.?1(Link) V38.?1(Link) V39.?1(Link) V40.?1(Link) V41.?1(Link) V42.?1(Link) V43.?1(Link) V44.?1(Link) V45.?1(Link) V46.?1(Link) V47.?1(Link) V740.0(Link) V741.0(Link) V742.0(Link) V743.0(Link) V877.?1(Link) V894.?1(Link) V895.?1(Link)
IscXStd: V11.?2(Link) V14.?2(Link) V21.?2(Link) V23.?2(Link) V48.0(Link) V53.0(Link) V55.0(Link) V57.0(Link) V59.?1(Link) V61.?1(Link)
IscYStd: V12.?2(Link) V15.?2(Link) V22.?2(Link) V24.?2(Link) V52.0(Link) V54.0(Link) V56.0(Link) V58.0(Link) V60.?1(Link) V65.?1(Link)
SqzCStd: V13.?2(Link) V20.?2(Link) V26.?2(Link) V66.0(Link) V67.0(Link) V69.0(Link) V70.0(Link) V71.0(Link) V72.0(Link) V73.0(Link) V77.0(Link) V78.?1(Link) V79.?1(Link) V80.?1(Link) V840.0(Link) V841.0(Link)
NetV1_?1: V1.?1 V16.?1
NetV2_?1: V2.?1 V17.?1
NetV3_?1: V3.?1 V18.?1
NetV4_?1: V4.?1 V19.?1
NetV5_?1: V5.?1 V20.?1
NetV6_?1: V6.?1 V21.?1
NetV7_?1: V7.?1 V22.?1
NetV8_?1: V8.?1 V23.?1
NetV9_?1: V9.?1 V24.?1
NetV10_?1: V10.?1 V26.?1
NetV11_?1: V11.?1 V27.?1
NetV12_?1: V12.?1 V28.?1
NetV13_?1: V13.?1 V29.?1
NetV14_?1: V14.?1 V30.?1
NetV15_?1: V15.?1 V31.?1

Not connected (* = marked no-connect by the designer): V32 Gain(INT)*; V33 Gain(INT)*; V34 PowerOk(BOOL)*; V35 ?1*; V36 PowerOk(BOOL)*; V37 PowerOk(BOOL)*; V38 PowerOk(BOOL)*; V39 PowerOk(BOOL)*; V40 PowerOk(BOOL)*; V41 PowerOk(BOOL)*; V42 PowerOk(BOOL)*; V43 PowerOk(BOOL)*; V44 PowerOk(BOOL)*; V45 PowerOk(BOOL)*; V46 PowerOk(BOOL)*; V47 PowerOk(BOOL)*; V48 Gain(INT)*; V52 Gain(INT)*; V53 Gain(INT)*; V54 Gain(INT)*; V55 Gain(INT)*; V56 Gain(INT)*; V57 Gain(INT)*; V58 Gain(INT)*; V59 PowerOk(BOOL)*; V60 PowerOk(BOOL)*; V61 PowerOk(BOOL)*; V65 PowerOk(BOOL)*; V66 Gain(INT)*; V67 Gain(INT)*; V69 Gain(INT)*; V70 Gain(INT)*; V71 Gain(INT)*; V72 Gain(INT)*; V73 Gain(INT)*; V77 Gain(INT)*; V78 PowerOk(BOOL)*; V79 PowerOk(BOOL)*; V80 PowerOk(BOOL)*; V740 Gain(INT)*; V741 Gain(INT)*; V742 Gain(INT)*; V743 Gain(INT)*; V840 Gain(INT)*; V841 Gain(INT)*; V877 PowerOk(BOOL)*; V894 PowerOk(BOOL)*; V895 PowerOk(BOOL)*

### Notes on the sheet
- EtherCAT Mapping: PLCs
- Daniel Sigg

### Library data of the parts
V1-V3 = VariableOutBOOL: BOOL; Instance: L1IscCorner Instance; PLC: L1IscCorner; Task: IscCStd
V4 = VariableOut: CornerPLC1toCornerPLC2Struct; Instance: L1AuxCorner Instance; PLC: L1AuxCorner; Task: AuxCStd
V5 = VariableOut: CornerPLC1toCornerPLC4Struct; Instance: L1AuxCorner Instance; PLC: L1AuxCorner; Task: AuxCStd
V6 V7 = VariableOut: CornerPLC1toEndStruct; Instance: L1AuxCorner Instance; PLC: L1AuxCorner; Task: AuxCStd
V8 V9 = VariableOut: CornerPLC2toEndStruct; Instance: L1IscCorner Instance; PLC: L1IscCorner; Task: IscCStd
V10 = VariableOut: CornerPLC2toCornerPLC4Struct; Instance: L1IscCorner Instance; PLC: L1IscCorner; Task: IscCStd
V11 V14 = VariableOut: EndtoCornerPLC2Struct; Instance: L1IscEndX Instance; PLC: L1IscEndX; Task: IscEStd
V12 V15 = VariableOut: EndtoCornerPLC2Struct; Instance: L1IscEndY Instance; PLC: L1IscEndY; Task: IscEStd
V13 = VariableOut: CornerPLC4toCornerPLC2Struct; Instance: L1SqzCorner Instance; PLC: L1SqzCorner; Task: SqzCStd
V16-V18 = VariableInBOOL: BOOL; Instance: L1AuxCorner Instance; PLC: L1AuxCorner; Task: AuxCStd
V19 = VariableIn: CornerPLC1toCornerPLC2Struct; Instance: L1IscCorner Instance; PLC: L1IscCorner; Task: IscCStd
V20 = VariableIn: CornerPLC1toCornerPLC4Struct; Instance: L1SqzCorner Instance; PLC: L1SqzCorner; Task: SqzCStd
V21 = VariableIn: CornerPLC1toEndStruct; Instance: L1IscEndX Instance; PLC: L1IscEndX; Task: IscEStd
V22 = VariableIn: CornerPLC1toEndStruct; Instance: L1IscEndY Instance; PLC: L1IscEndY; Task: IscEStd
V23 = VariableIn: CornerPLC2toEndStruct; Instance: L1IscEndX Instance; PLC: L1IscEndX; Task: IscEStd
V24 = VariableIn: CornerPLC2toEndStruct; Instance: L1IscEndY Instance; PLC: L1IscEndY; Task: IscEStd
V26 = VariableIn: CornerPLC2toCornerPLC4Struct; Instance: L1SqzCorner Instance; PLC: L1SqzCorner; Task: SqzCStd
V27 V28 = VariableIn: EndtoCornerPLC2Struct; Instance: L1AuxCorner Instance; PLC: L1AuxCorner; Task: AuxCStd
V29 = VariableIn: CornerPLC4toCornerPLC2Struct; Instance: L1IscCorner Instance; PLC: L1IscCorner; Task: IscCStd
V30 V31 = VariableIn: EndtoCornerPLC2Struct; Instance: L1IscCorner Instance; PLC: L1IscCorner; Task: IscCStd
V32 V33 = DCPower_DCPowerOutStruct: DCPowerOutStruct; BoxType: Variable; Instance: L1AuxCorner Instance; PLC: L1AuxCorner; Task: AuxCStd
V34 V36-V47 V877 V894 V895 = Demodulator_DemodulatorOutStruct: DemodulatorOutStruct; BoxType: Variable; Instance: L1IscCorner Instance; PLC: L1IscCorner; Task: IscCStd
V35 = VariableOut: FiberDistributionOutStruct; Instance: L1IscCorner Instance; PLC: L1IscCorner; Task: IscCStd
V48 V53 V55 V57 = DCPower_DCPowerOutStruct: DCPowerOutStruct; BoxType: Variable; Instance: L1IscEndX Instance; PLC: L1IscEndX; Task: IscEStd
V52 V54 V56 V58 = DCPower_DCPowerOutStruct: DCPowerOutStruct; BoxType: Variable; Instance: L1IscEndY Instance; PLC: L1IscEndY; Task: IscEStd
V59 V61 = Demodulator_DemodulatorOutStruct: DemodulatorOutStruct; BoxType: Variable; Instance: L1IscEndX Instance; PLC: L1IscEndX; Task: IscEStd
V60 V65 = Demodulator_DemodulatorOutStruct: DemodulatorOutStruct; BoxType: Variable; Instance: L1IscEndY Instance; PLC: L1IscEndY; Task: IscEStd
V66 V67 V69-V73 V77 V840 V841 = DCPower_DCPowerOutStruct: DCPowerOutStruct; BoxType: Variable; Instance: L1SqzCorner Instance; PLC: L1SqzCorner; Task: SqzCStd
V78-V80 = Demodulator_DemodulatorOutStruct: DemodulatorOutStruct; BoxType: Variable; Instance: L1SqzCorner Instance; PLC: L1SqzCorner; Task: SqzCStd
V740-V743 = DCPower_DCPowerOutStruct: DCPowerOutStruct; BoxType: Variable; Instance: L1IscCorner Instance; PLC: L1IscCorner; Task: IscCStd

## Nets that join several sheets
AuxCFast: H1IfoSystem (T31.0), H1Top2 (8 pins), IfoMsr1 (6 pins), IfoPsl (V513.0 V515.0), IfoIsc2A (16 pins), IfoIsc2B (12 pins), IfoEndX0 (V530.?1 V531.?1 V533.?1 V534.?1), IfoEndY0 (V622.?1 V623.?1 V624.?1 V625.?1), IfoFcEnd (V855.0 V857.0)
AuxCStd: H1IfoSystem (T30.0), H1Top2 (8 pins), IfoMsr1 (7 pins), IfoAux1 (22 pins), IfoPsl (12 pins), IfoIsc2A (24 pins), IfoIsc2B (24 pins), IfoIsc4 (16 pins), IfoIsc5A (49 pins), IfoIsc6 (V420.1 V421.1 V908.1 V909.1), IfoSqz4A (22 pins), IfoFcEnd (9 pins), IfoTop1 (11 pins)
AuxXFast: H1IfoSystem (T33.0), IfoEndX2 (V573.0 V575.0 V576.0 V578.0)
AuxXStd: H1IfoSystem (T32.0), IfoEndX0 (V526.?2 V527.?2 V845.?1 V846.?1), IfoEndX2 (19 pins), IfoEndXAux (10 pins)
AuxYFast: H1IfoSystem (T35.0), IfoEndY2 (V665.0 V667.0 V669.0 V671.0)
AuxYStd: H1IfoSystem (T34.0), IfoEndY0 (V618.?2 V619.?2 V847.?1 V848.?1), IfoEndY2 (19 pins), IfoEndYAux (10 pins)
IscCFast: H1IfoSystem (T10.0), IfoIsc5A (5 pins)
IscCStd: H1IfoSystem (T9.0), IfoPsl (V509.0 V510.0), IfoIsc1 (16 pins), IfoIsc2A (V164.?1 V170.?1), IfoIsc3 (57 pins), IfoIsc4 (48 pins), IfoIsc5A (50 pins), IfoIsc5B (8 pins), IfoIsc6 (42 pins), IfoTop1 (31 pins)
IscXStd: H1IfoSystem (T11.0), IfoEndX0 (V528.?1 V529.?1), IfoEndX1 (16 pins), IfoEndX2 (38 pins), IfoEndX3 (6 pins), IfoEndXAux (V556.1), IfoTop1 (10 pins)
IscYStd: H1IfoSystem (T13.0), IfoEndY0 (V620.?1 V621.?1), IfoEndY1 (16 pins), IfoEndY2 (38 pins), IfoEndY3 (6 pins), IfoEndYAux (V649.1), IfoTop1 (10 pins)
SqzCFast: H1IfoSystem (T16.0), IfoIsc3 (V288.0), IfoSqz2 (11 pins), IfoSqz3A (V486.1 V495.1 V874.1), IfoSqz3B (V735.1)
SqzCStd: H1IfoSystem (T15.0), IfoIsc3 (18 pins), IfoSqz1 (16 pins), IfoSqz2 (35 pins), IfoSqz3A (78 pins), IfoSqz3B (25 pins), IfoSqz4A (21 pins), IfoSqz4B (17 pins), IfoFcEnd (8 pins), IfoSqz5 (9 pins), IfoTop1 (16 pins)
TcsCFast: H1IfoSystem (T37.0), IfoPsl (8 pins)
TcsCStd: H1IfoSystem (T27.0), IfoAux1 (8 pins), IfoPsl (31 pins), IfoTcs1 (29 pins)
TcsXStd: H1IfoSystem (T28.0), IfoEndX2 (5 pins), IfoEndX3 (V584.0 V584.1 V585.0 V585.1), IfoEndXAux (V608.?1 V609.?1)
TcsYStd: H1IfoSystem (T29.0), IfoEndY2 (5 pins), IfoEndY3 (V678.0 V678.1 V679.0 V679.1), IfoEndYAux (V695.?1 V700.?1)
ISC2M: IfoIsc2A (B106.Ebus), IfoIsc2B (B121.Ebus)
ISC2R: IfoIsc2A (B120.Ebus), IfoIsc2B (B134.Ebus)
ISC5R: IfoIsc5A (B288.Ebus), IfoIsc5B (B289.Ebus)
NetB70_X2 Out: IfoIsc1 (B70.X2 Out), IfoIsc2A (B86.?2)
NetB107_X2 Out: IfoIsc2A (B107.X2 Out), IfoIsc3 (B147.X1 In)
NetB175_X2 Out: IfoIsc3 (B175.X2 Out), IfoIsc4 (B197.X1 In)
NetB234_X2 Out: IfoIsc4 (B234.X2 Out), IfoIsc5A (B240.X1 In)
NetB275_X2 Out: IfoIsc5A (B275.X2 Out), IfoIsc6 (B309.X1 In)
NetB409_X2 Out: IfoSqz1 (B409.X2 Out), IfoSqz2 (B425.X1 In)
NetB473_X2 Out: IfoSqz2 (B473.X2 Out), IfoSqz3A (B494.X1 In)
NetB554_X2 Out: IfoPsl (B554.X2 Out), IfoTcs1 (B563.X1 In)
NetB611_X1: IfoEndX0 (B611.X1), IfoEndX1 (B616.X1 In), IfoEndY0 (B750.X1), IfoEndY1 (B755.X1 In)
NetB616_X2 Out: IfoEndX1 (B616.X2 Out), IfoEndY1 (B755.X2 Out), IfoEndXAux (B742.X1), IfoEndYAux (B880.X1)
NetB658_X2 Out: IfoEndX1 (B658.X2 Out), IfoEndX2 (B674.X1 In), IfoEndY1 (B797.X2 Out), IfoEndY2 (B813.X1 In)
NetB710_X2 Out: IfoEndX2 (B710.X2 Out), IfoEndX3 (B724.X1 In), IfoEndY2 (B849.X2 Out), IfoEndY3 (B863.X1 In)
NetB738_Output: IfoEndX2 (V549.SledShutDown), IfoEndY2 (V642.SledShutDown), IfoEndXAux (B738.Output), IfoEndYAux (B877.Output)
NetB746#2_X1 In: IfoSqz4A (B958.X2 Out), IfoSqz5 (B746#2.X1 In)
NetB886_X2 Out: IfoSqz3B (B886.X2 Out), IfoSqz4A (B910.X1 In)
NetV453_1: IfoSqz2 (V453.1), IfoSqz3A (V498.1 V500.1 V503.?2)
NetV454_1: IfoSqz2 (V454.1), IfoSqz3A (V499.1 V501.1 V502.?2)
SQZ3L: IfoSqz3A (B512C.Ebus), IfoSqz3B (B884A.Ebus)
SQZ3R: IfoSqz3A (B513.X2 Out), IfoSqz3B (B886.X1 In)
SQZ4L: IfoSqz4A (B938.Ebus), IfoSqz4B (B928.Ebus)
SQZ4M: IfoSqz4A (B945.Ebus), IfoSqz4B (B961A.Ebus)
